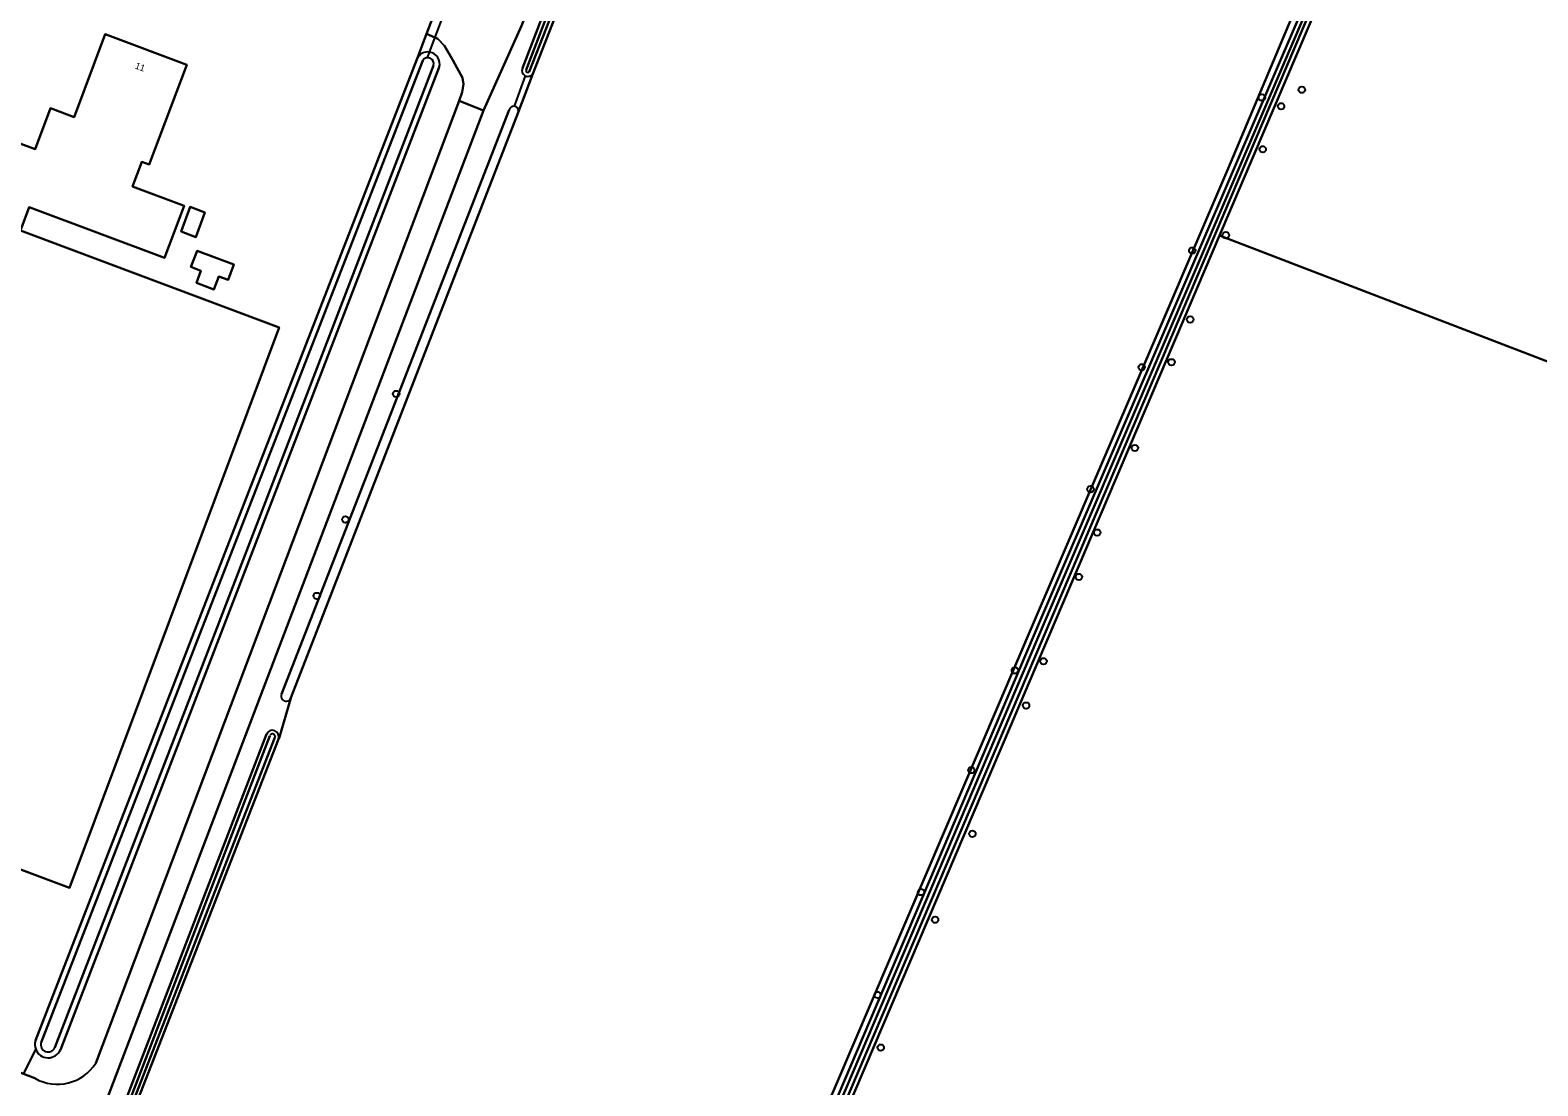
# Model space of a CAD drawing. Extents: x 155209 to 156748, y 385356 to 388487.
# Drawn here: x 155768.7 to 155996.7, y 386429.5 to 386589.2 of the extents above; entities that cross this region are included whole.
import ezdxf

# ---------------------------------------------------------------- set-up
doc = ezdxf.new("R2010")
doc.units = 0
for name, color, linetype in [('IMGEO_Boom', 7, 'Continuous'), ('IMGEO_Bouwland', 7, 'Continuous'), ('IMGEO_Duiker', 7, 'Continuous'), ('IMGEO_Erf', 7, 'Continuous'), ('IMGEO_Grasland_overig', 7, 'Continuous'), ('IMGEO_Hek', 7, 'Continuous'), ('IMGEO_Loofbos', 7, 'Continuous'), ('IMGEO_Oever', 7, 'Continuous'), ('IMGEO_Pand', 7, 'Continuous'), ('IMGEO_Pand_nummerreeks', 7, 'Continuous'), ('IMGEO_Rijbaan_lokaal_onverhard', 7, 'Continuous'), ('IMGEO_Rijbaan_lokaal_open', 7, 'Continuous'), ('IMGEO_Waterloop', 7, 'Continuous')]:
    doc.layers.add(name, color=color, linetype=linetype)

msp = doc.modelspace()

# ---------------------------------------------------------------- linework, layer by layer
at = {"layer": 'IMGEO_Boom'}
for centre in [(155954.93, 386578.99), (155960.98, 386580.15), (155957.84, 386577.64), (155955.06, 386571.14), (155949.48, 386558.16), (155944.41, 386555.82), (155944.09, 386545.41), (155936.76, 386538.18), (155941.26, 386538.94), (155824.02, 386534.15), (155935.73, 386525.98), (155929.03, 386519.76), (155816.35, 386515.16), (155930.04, 386513.19), (155927.27, 386506.48), (155812.04, 386503.61), (155921.91, 386493.73), (155917.59, 386492.36), (155919.28, 386487.03), (155911, 386477.28), (155911.16, 386467.64), (155903.4, 386458.84), (155905.52, 386454.66), (155896.83, 386443.28), (155897.3, 386435.32)]:
    msp.add_circle(centre, 0.489, dxfattribs=at)
at = {"layer": 'IMGEO_Bouwland'}
for points in [[(155920.62, 386500), (155949.82, 386568.26), (155965.82, 386606.23), (155869.01, 386643.44), (155864.71, 386632.61), (155864.34, 386632.76), (155844.68, 386582.56), (155842.49, 386576.7), (155812.69, 386500), (155808.11, 386488.2), (155808.11, 386488.16), (155806.31, 386482.13), (155806.23, 386481.98), (155776.16, 386404.85), (155770.45, 386390.2), (155742.01, 386316.6), (155739.62, 386308.66), (155823.47, 386270.87), (155882.29, 386410.38)], [(156111.26, 386456.76), (156125.52, 386490.13), (155948.54, 386558.13), (155923.76, 386500), (155881.05, 386399.78), (156052.24, 386324.4), (156054.54, 386323.39), (156054.72, 386323.81), (156066.59, 386351.85), (156087.98, 386402.17)]]:
    msp.add_lwpolyline(points, close=True, dxfattribs=at)
msp.add_lwpolyline([(156000, 386618.39), (155978.88, 386626.57), (155978.5, 386626.55), (155977.56, 386625.78), (155975.89, 386622.61), (155965.41, 386597.71), (155948.54, 386558.13), (156125.52, 386490.13)], dxfattribs=at)
at = {"layer": 'IMGEO_Duiker'}
for points in [[(155828.8, 386585.14), (155829.07, 386585.85), (155833.17, 386596.64), (155833.53, 386597.6)], [(155843.52, 386582.27), (155841.88, 386577.65)]]:
    msp.add_lwpolyline(points, dxfattribs=at)
at = {"layer": 'IMGEO_Erf'}
for points in [[(155827.24, 386584.98), (155828.63, 386588.62), (155831.1, 386595.08), (155832.48, 386598.7), (155858.39, 386666.09), (155860.17, 386671.06), (155845.78, 386676.56), (155815.75, 386688.47), (155811.53, 386686.69), (155808.55, 386689.62), (155807.95, 386691.6), (155784.6, 386700.46), (155766.42, 386707.35), (155764.8, 386707.96), (155764.04, 386705.95)], [(155769.48, 386436.4), (155794.21, 386500), (155827.24, 386584.98)], [(155681.71, 386464.25), (155683.21, 386463.62), (155722.75, 386448.47), (155767.68, 386431.34), (155769.52, 386435.08)]]:
    msp.add_lwpolyline(points, dxfattribs=at)
for points in [[(155759.25, 386561.86), (155760.53, 386565.29), (155758.67, 386565.98), (155761.68, 386574.04), (155769.44, 386571.14), (155771.76, 386577.35), (155775.31, 386576.02), (155780, 386588.55), (155792.35, 386583.93), (155786.69, 386568.83), (155785.55, 386569.26), (155784.14, 386565.5), (155791.95, 386562.57), (155789.02, 386554.73), (155768.53, 386562.4), (155767.21, 386558.86), (155806.34, 386544.21), (155789.79, 386500), (155774.62, 386459.47), (155689.46, 386491.38), (155692.69, 386500), (155721.18, 386576.11)], [(155792.9, 386562.42), (155795.11, 386561.59), (155793.72, 386557.86), (155791.5, 386558.69)], [(155794.51, 386552.79), (155793, 386553.35), (155793.05, 386553.48), (155793.91, 386555.79), (155799.49, 386553.71), (155798.62, 386551.38), (155797.19, 386551.91), (155796.46, 386549.96), (155793.82, 386550.95)]]:
    msp.add_lwpolyline(points, close=True, dxfattribs=at)
msp.add_arc((155771.41, 386435.79), 2.02, 162.564, 200.4945, dxfattribs=at)
at = {"layer": 'IMGEO_Grasland_overig'}
for points in [[(155843.12, 386583.39), (155862.38, 386633.54), (155860.74, 386634.19), (155842.99, 386589.8), (155837.24, 386577.02), (155807.91, 386500), (155780.04, 386426.8), (155770.92, 386403.12), (155764.64, 386405.34), (155770.07, 386419.5)], [(155823.99, 386270.66), (155835.41, 386297.82), (155921.47, 386500), (155974.31, 386623.3)], [(155965.82, 386606.23), (155949.82, 386568.26), (155920.62, 386500), (155882.29, 386410.38), (155823.47, 386270.87), (155739.62, 386308.66), (155738.01, 386309.39), (155727.77, 386314.74), (155725.94, 386310.97), (155725.74, 386310.58), (155732.88, 386307.56), (155733.51, 386308.8), (155732.83, 386309.11)], [(155842.49, 386576.7), (155844.68, 386582.56)], [(155806.67, 386488.75), (155811.05, 386500), (155841.12, 386577.09)], [(155806.23, 386481.98), (155806.31, 386482.13), (155808.11, 386488.16), (155808.11, 386488.2)], [(155774.73, 386405.55), (155804.41, 386482.69)]]:
    msp.add_lwpolyline(points, dxfattribs=at)
for centre, radius, start, end in [((155843.94, 386583.05), 0.887, 157.1718, 241.7029), ((155843.94, 386583.05), 0.886, 241.6544, 326.2784), ((155841.82, 386576.93), 0.716, 84.7897, 167.274), ((155841.81, 386576.93), 0.719, 341.1196, 84.5705), ((155807.38, 386488.45), 0.771, 156.4503, 341.3839), ((155805.32, 386482.32), 0.974, 339.607, 158.1448)]:
    msp.add_arc(centre, radius, start, end, dxfattribs=at)
at = {"layer": 'IMGEO_Hek'}
msp.add_lwpolyline([(155920.62, 386500), (155882.29, 386410.38), (155823.47, 386270.87), (155739.62, 386308.66), (155738.01, 386309.39), (155727.77, 386314.74), (155725.94, 386310.97)], dxfattribs=at)
at = {"layer": 'IMGEO_Loofbos'}
for points in [[(155833.54, 386578.47), (155834.03, 386579.78), (155834.21, 386580.97), (155834.05, 386581.94), (155832.62, 386584.62), (155831.32, 386586.8), (155830.35, 386587.85), (155828.63, 386588.62), (155827.24, 386584.98)], [(155830.54, 386583.55), (155798.32, 386500), (155773.25, 386434.99)], [(155778.59, 386432.99), (155803.9, 386500), (155833.54, 386578.47)], [(155769.52, 386435.08), (155767.68, 386431.34), (155769.39, 386430.69)]]:
    msp.add_lwpolyline(points, dxfattribs=at)
for centre, radius, start, end in [((155828.8, 386584.05), 1.81, 81.3767, 149.2995), ((155828.8, 386584.05), 1.81, 343.8217, 81.2949), ((155771.4, 386435.79), 2.01, 200.5255, 336.5283), ((155772.78, 386436.69), 6.9, 240.6194, 327.5146)]:
    msp.add_arc(centre, radius, start, end, dxfattribs=at)
at = {"layer": 'IMGEO_Oever'}
for points in [[(155872.64, 386660.8), (155862.38, 386633.54), (155843.12, 386583.39)], [(155843.67, 386583.14), (155862.92, 386633.26), (155862.93, 386633.28), (155862.93, 386633.29), (155862.94, 386633.31), (155862.98, 386633.39), (155863, 386633.47), (155863.03, 386633.55), (155873.19, 386660.57)], [(155874.25, 386660.14), (155863.79, 386632.98), (155844.15, 386582.85)], [(155844.68, 386582.56), (155864.34, 386632.76)], [(155974.31, 386623.3), (155921.47, 386500), (155835.41, 386297.82), (155823.99, 386270.66)], [(155975.25, 386622.84), (155964.78, 386597.98), (155947.92, 386558.4), (155923.14, 386500.27), (155880.42, 386400.05), (155849.68, 386328.06), (155848.56, 386325.43), (155836.13, 386296.33), (155824.53, 386268.38)], [(155824.6, 386270.34), (155836.03, 386297.56), (155922.1, 386499.73), (155974.91, 386622.99)], [(155825.15, 386268.11), (155836.76, 386296.06), (155849.19, 386325.17), (155850.31, 386327.79), (155881.05, 386399.78), (155923.76, 386500), (155948.54, 386558.13), (155965.41, 386597.71), (155975.89, 386622.61)], [(155827.24, 386584.98), (155794.21, 386500), (155769.48, 386436.4)], [(155770.33, 386436.1), (155795.04, 386499.68), (155828.04, 386584.58)], [(155829.69, 386583.83), (155797.49, 386500.32), (155772.43, 386435.33)], [(155773.25, 386434.99), (155798.32, 386500), (155830.54, 386583.55)], [(155804.41, 386482.69), (155774.73, 386405.55)], [(155775.26, 386405.36), (155804.94, 386482.48)], [(155805.7, 386482.19), (155775.67, 386405.13)], [(155776.16, 386404.85), (155806.23, 386481.98)]]:
    msp.add_lwpolyline(points, dxfattribs=at)
for centre, radius, start, end in [((155828.8, 386584.05), 1.81, 81.3767, 149.2995), ((155828.8, 386584.05), 1.81, 343.8217, 81.2949), ((155828.8, 386584.06), 0.921, 345.7483, 145.6148), ((155843.94, 386583.05), 0.887, 157.1718, 241.7029), ((155843.94, 386583.05), 0.289, 160.7637, 316.7521), ((155843.94, 386583.05), 0.886, 241.6544, 326.2784), ((155805.32, 386482.32), 0.974, 339.607, 158.1448), ((155805.32, 386482.34), 0.411, 338.8976, 159.0774), ((155771.41, 386435.79), 2.02, 162.564, 200.4945), ((155771.4, 386435.79), 2.01, 200.5255, 336.5283), ((155771.4, 386435.79), 1.12, 163.5186, 335.9736)]:
    msp.add_arc(centre, radius, start, end, dxfattribs=at)
at = {"layer": 'IMGEO_Pand'}
for points in [[(155774.62, 386459.47), (155789.79, 386500), (155806.34, 386544.21), (155767.21, 386558.86), (155768.53, 386562.4), (155789.02, 386554.73), (155791.95, 386562.57), (155784.14, 386565.5), (155785.55, 386569.26), (155786.69, 386568.83), (155792.35, 386583.93), (155780, 386588.55), (155775.31, 386576.02), (155771.76, 386577.35), (155769.44, 386571.14), (155761.68, 386574.04), (155758.67, 386565.98), (155760.53, 386565.29), (155759.25, 386561.86), (155721.18, 386576.11), (155692.69, 386500), (155689.46, 386491.38)], [(155791.5, 386558.69), (155793.72, 386557.86), (155795.11, 386561.59), (155792.9, 386562.42)], [(155793.05, 386553.48), (155793, 386553.35), (155794.51, 386552.79), (155793.82, 386550.95), (155796.46, 386549.96), (155797.19, 386551.91), (155798.62, 386551.38), (155799.49, 386553.71), (155793.91, 386555.79)]]:
    msp.add_lwpolyline(points, close=True, dxfattribs=at)
at = {"layer": 'IMGEO_Rijbaan_lokaal_onverhard'}
for points in [[(155770.07, 386419.5), (155764.64, 386405.34), (155770.92, 386403.12), (155780.04, 386426.8), (155807.91, 386500), (155837.24, 386577.02), (155833.54, 386578.47), (155803.9, 386500), (155778.59, 386432.99)], [(155769.39, 386430.69), (155767.68, 386431.34), (155722.75, 386448.47), (155683.21, 386463.62), (155681.71, 386464.25)]]:
    msp.add_lwpolyline(points, dxfattribs=at)
msp.add_arc((155772.78, 386436.69), 6.9, 240.6194, 327.5146, dxfattribs=at)
at = {"layer": 'IMGEO_Rijbaan_lokaal_open'}
msp.add_lwpolyline([(155860.74, 386634.19), (155873.72, 386666.78), (155868.05, 386669), (155867.81, 386668.39), (155855.14, 386636.42), (155840.59, 386598.69), (155839.46, 386597.18), (155836.9, 386595.99), (155834.97, 386595.48), (155833.27, 386595.02), (155831.1, 386595.08), (155828.63, 386588.62), (155830.35, 386587.85), (155831.32, 386586.8), (155832.62, 386584.62), (155834.05, 386581.94), (155834.21, 386580.97), (155834.03, 386579.78), (155833.54, 386578.47), (155837.24, 386577.02), (155842.99, 386589.8)], close=True, dxfattribs=at)
at = {"layer": 'IMGEO_Waterloop'}
for points in [[(155873.19, 386660.57), (155863.03, 386633.55), (155863, 386633.47), (155862.98, 386633.39), (155862.94, 386633.31), (155862.93, 386633.29), (155862.93, 386633.28), (155862.92, 386633.26), (155843.67, 386583.14)], [(155844.15, 386582.85), (155863.79, 386632.98), (155874.25, 386660.14)], [(155824.53, 386268.38), (155836.13, 386296.33), (155848.56, 386325.43), (155849.68, 386328.06), (155880.42, 386400.05), (155923.14, 386500.27), (155947.92, 386558.4), (155964.78, 386597.98), (155975.25, 386622.84)], [(155974.91, 386622.99), (155922.1, 386499.73), (155836.03, 386297.56), (155824.6, 386270.34)], [(155828.04, 386584.58), (155795.04, 386499.68), (155770.33, 386436.1)], [(155772.43, 386435.33), (155797.49, 386500.32), (155829.69, 386583.83)], [(155841.12, 386577.09), (155811.05, 386500), (155806.67, 386488.75)], [(155808.11, 386488.2), (155812.69, 386500), (155842.49, 386576.7)], [(155804.94, 386482.48), (155775.26, 386405.36)], [(155775.67, 386405.13), (155805.7, 386482.19)]]:
    msp.add_lwpolyline(points, dxfattribs=at)
for centre, radius, start, end in [((155828.8, 386584.06), 0.921, 345.7483, 145.6148), ((155843.94, 386583.05), 0.289, 160.7637, 316.7521), ((155841.82, 386576.93), 0.716, 84.7897, 167.274), ((155841.81, 386576.93), 0.719, 341.1196, 84.5705), ((155807.38, 386488.45), 0.771, 156.4503, 341.3839), ((155805.32, 386482.34), 0.411, 338.8976, 159.0774), ((155771.4, 386435.79), 1.12, 163.5186, 335.9736)]:
    msp.add_arc(centre, radius, start, end, dxfattribs=at)

# ---------------------------------------------------------------- texts
at = {"layer": 'IMGEO_Pand_nummerreeks'}
msp.add_text('11', height=1, rotation=339.4791, dxfattribs=at).set_placement((155784.44, 386583.39))

doc.saveas('drawing.dxf')
